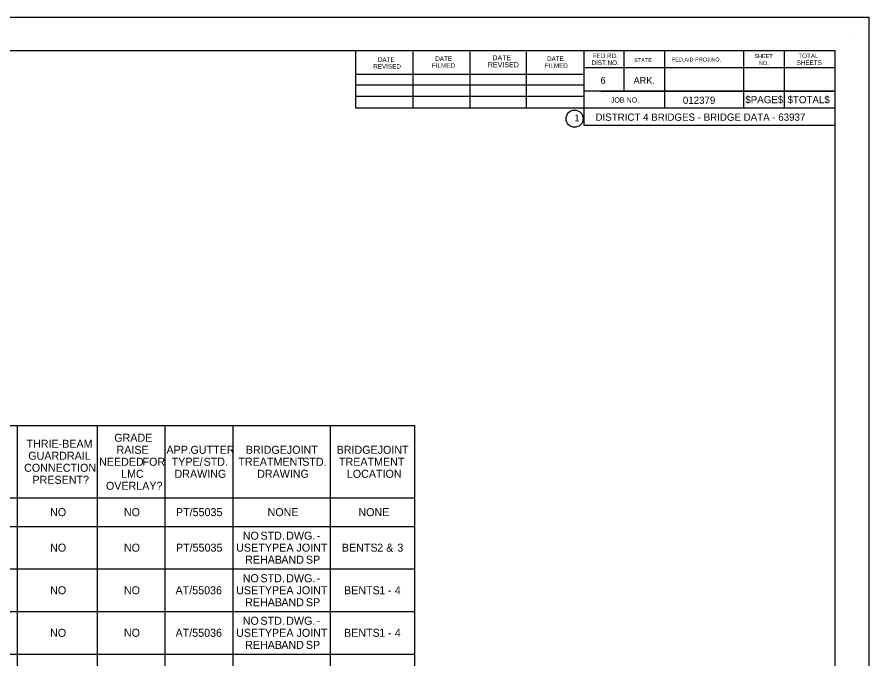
# Model space of a CAD drawing. Extents: x 16 to 1228740, y 11 to 152440.
# Drawn here: x 17.273 to 18.49, y 11.626 to 12.543 of the extents above; entities that cross this region are included whole.
import ezdxf

# ---------------------------------------------------------------- set-up
doc = ezdxf.new("R2010")
doc.units = 0
for name, color, linetype in [('B_Copy In', 7, 'Continuous'), ('B_Text', 7, 'Continuous'), ('R_Border', 7, 'Continuous')]:
    doc.layers.add(name, color=color, linetype=linetype)

msp = doc.modelspace()

# ---------------------------------------------------------------- linework, layer by layer
at = {"layer": 'B_Text'}
for p, q in [((16.3546, 11.9591), (17.8411, 11.9591)), ((17.2733, 11.2432), (17.2733, 11.9591)), ((17.3879, 11.2432), (17.3879, 11.9591)), ((17.4842, 11.2432), (17.4842, 11.9591)), ((17.5815, 11.2432), (17.5815, 11.9591)), ((17.7205, 11.2432), (17.7205, 11.9591)), ((17.8411, 11.2432), (17.8411, 11.9591)), ((16.3546, 11.8557), (17.8411, 11.8557)), ((16.3546, 11.8151), (17.8411, 11.8151)), ((16.3546, 11.7543), (17.8411, 11.7543)), ((16.3546, 11.6934), (17.8411, 11.6934)), ((16.3546, 11.6326), (17.8411, 11.6326))]:
    msp.add_line(p, q, dxfattribs=at)
at = {"layer": 'R_Border'}
for p, q in [((18.4604, 12.514), (18.4604, 12.514)), ((15.7833, 12.4948), (18.4422, 12.4948)), ((17.7567, 12.4124), (17.7567, 12.4948)), ((17.8389, 12.4124), (17.8389, 12.4931)), ((17.9202, 12.4124), (17.9202, 12.4931)), ((18.0009, 12.4124), (18.0009, 12.4931)), ((18.083, 12.4948), (18.083, 12.3881)), ((18.14, 12.4948), (18.14, 12.4369)), ((18.1979, 12.4948), (18.1979, 12.4124)), ((18.311, 12.4948), (18.311, 12.4124)), ((18.3689, 12.4948), (18.3689, 12.4124)), ((18.4422, 10.7576), (18.4422, 12.4948)), ((18.4422, 12.4703), (18.083, 12.4703)), ((18.4422, 12.4704), (18.4422, 12.4704)), ((17.7567, 12.4613), (18.083, 12.4613)), ((17.7567, 12.4458), (18.083, 12.4458)), ((18.4422, 12.4369), (18.083, 12.4369)), ((18.1077, 12.4369), (18.4422, 12.4369)), ((17.7567, 12.4124), (17.7567, 12.4296)), ((17.7567, 12.4296), (18.083, 12.4296)), ((18.4422, 12.4124), (17.7567, 12.4124)), ((18.083, 12.3881), (18.4422, 12.3881)), ((18.083, 12.3881), (18.4422, 12.3881))]:
    msp.add_line(p, q, dxfattribs=at)
msp.add_lwpolyline([(15.6569, 12.5428), (18.4903, 12.5428), (18.4903, 10.7095), (15.6569, 10.7095)], close=True, dxfattribs=at)
msp.add_circle((18.0696, 12.3976), 0.0122, dxfattribs=at)

# ---------------------------------------------------------------- texts
at = {"layer": 'B_Copy In'}
msp.add_text('DISTRICT 4 BRIDGES - BRIDGE DATA - 63937', height=0.0104, dxfattribs=at).set_placement((18.0995, 12.3946))
at = {"layer": 'B_Text'}
for s, p in [('GRADE', (17.4117, 11.936)), ('THRIE-BEAM', (17.2863, 11.9274)), ('GUARDRAIL', (17.2888, 11.9103)), ('RAISE', (17.415, 11.9188)), ('APP.', (17.4863, 11.9188)), (' GUTTER', (17.5164, 11.9188)), ('BRIDGE', (17.5997, 11.9188)), (' JOINT', (17.6541, 11.9188)), ('BRIDGE', (17.7295, 11.9188)), (' JOINT', (17.7839, 11.9188)), ('NEEDED', (17.39, 11.9017)), (' FOR', (17.4478, 11.9017)), ('TYPE/', (17.4938, 11.9017)), (' STD.', (17.5351, 11.9017)), ('TREATMENT', (17.5891, 11.9017)), (' STD.', (17.6761, 11.9017)), ('TREATMENT', (17.7329, 11.9017)), ('CONNECTION', (17.2829, 11.8931)), ('LMC', (17.4215, 11.8845)), ('DRAWING', (17.4978, 11.8845)), ('DRAWING', (17.6159, 11.8845)), ('LOCATION', (17.7441, 11.8845)), ('PRESENT?', (17.2948, 11.8759)), ('OVERLAY?', (17.3998, 11.8674)), ('NO', (17.32, 11.8297)), ('NO', (17.4255, 11.8297)), ('PT/55035', (17.4999, 11.8297)), ('NONE', (17.6308, 11.8297)), ('NONE', (17.7606, 11.8297)), ('NO', (17.5953, 11.7961)), (' STD.', (17.6164, 11.7961)), (' DWG.', (17.6532, 11.7961)), (' -', (17.6968, 11.7961)), ('NO', (17.32, 11.779)), ('NO', (17.4255, 11.779)), ('PT/55035', (17.4999, 11.779)), ('USE', (17.5859, 11.779)), (' TYPE', (17.6133, 11.779)), (' A', (17.6535, 11.779)), (' JOINT', (17.6679, 11.779)), ('BENTS', (17.737, 11.779)), (' 2', (17.7832, 11.779)), (' &', (17.796, 11.779)), (' 3', (17.812, 11.779)), ('REHAB', (17.5987, 11.7618)), (' AND', (17.6462, 11.7618)), (' SP', (17.6813, 11.7618)), ('NO', (17.5953, 11.7353)), (' STD.', (17.6164, 11.7353)), (' DWG.', (17.6532, 11.7353)), (' -', (17.6968, 11.7353)), ('NO', (17.32, 11.7181)), ('NO', (17.4255, 11.7181)), ('AT/55036', (17.4993, 11.7181)), ('USE', (17.5859, 11.7181)), (' TYPE', (17.6133, 11.7181)), (' A', (17.6535, 11.7181)), (' JOINT', (17.6679, 11.7181)), ('BENTS', (17.7401, 11.7181)), (' 1', (17.7862, 11.7181)), (' 4', (17.8084, 11.7181)), (' -', (17.7985, 11.7181)), ('REHAB', (17.5987, 11.701)), (' AND', (17.6462, 11.701)), (' SP', (17.6813, 11.701)), ('NO', (17.5953, 11.6745)), (' STD.', (17.6164, 11.6745)), (' DWG.', (17.6532, 11.6745)), (' -', (17.6968, 11.6745)), ('NO', (17.32, 11.6573)), ('NO', (17.4255, 11.6573)), ('AT/55036', (17.4993, 11.6573)), ('USE', (17.5859, 11.6573)), (' TYPE', (17.6133, 11.6573)), (' A', (17.6535, 11.6573)), (' JOINT', (17.6679, 11.6573)), ('BENTS', (17.7401, 11.6573)), (' 1', (17.7862, 11.6573)), (' 4', (17.8084, 11.6573)), (' -', (17.7985, 11.6573)), ('REHAB', (17.5987, 11.6401)), (' AND', (17.6462, 11.6401)), (' SP', (17.6813, 11.6401))]:
    msp.add_text(s, height=0.01144, dxfattribs=at).set_placement(p)
at = {"layer": 'R_Border'}
for s, height, p in [('DATE', 0.00652, (17.7885, 12.4788)), ('DATE', 0.00652, (17.8705, 12.4801)), ('DATE', 0.00733, (17.952, 12.4809)), ('DATE', 0.00652, (18.0302, 12.4801)), ('DIST.NO.', 0.00652, (18.0937, 12.4743)), ('FED.RD.', 0.00652, (18.0954, 12.4841)), ('STATE', 0.0057, (18.1547, 12.4784)), ('FED.AID PROJ.NO.', 0.0057, (18.2085, 12.4793)), ('SHEET', 0.0057, (18.3265, 12.4841)), ('NO.', 0.0057, (18.333, 12.4743)), ('SHEETS', 0.00652, (18.3869, 12.4743)), ('TOTAL', 0.00652, (18.3892, 12.4841)), ('REVISED', 0.00652, (17.7818, 12.4691)), ('FILMED', 0.00652, (17.8657, 12.4703)), ('REVISED', 0.00733, (17.9455, 12.4711)), ('FILMED', 0.00652, (18.0269, 12.4703)), ('6', 0.00977, (18.1067, 12.4474)), ('ARK.', 0.00977, (18.1539, 12.4474)), ('JOB NO.', 0.00733, (18.1214, 12.4206)), ('012379', 0.0104, (18.2243, 12.4187)), ('$PAGE$', 0.0104, (18.3136, 12.4196)), ('$TOTAL$', 0.0104, (18.3739, 12.4196)), ('1', 0.00977, (18.0693, 12.3937))]:
    msp.add_text(s, height=height, dxfattribs=at).set_placement(p)

doc.saveas('drawing.dxf')
